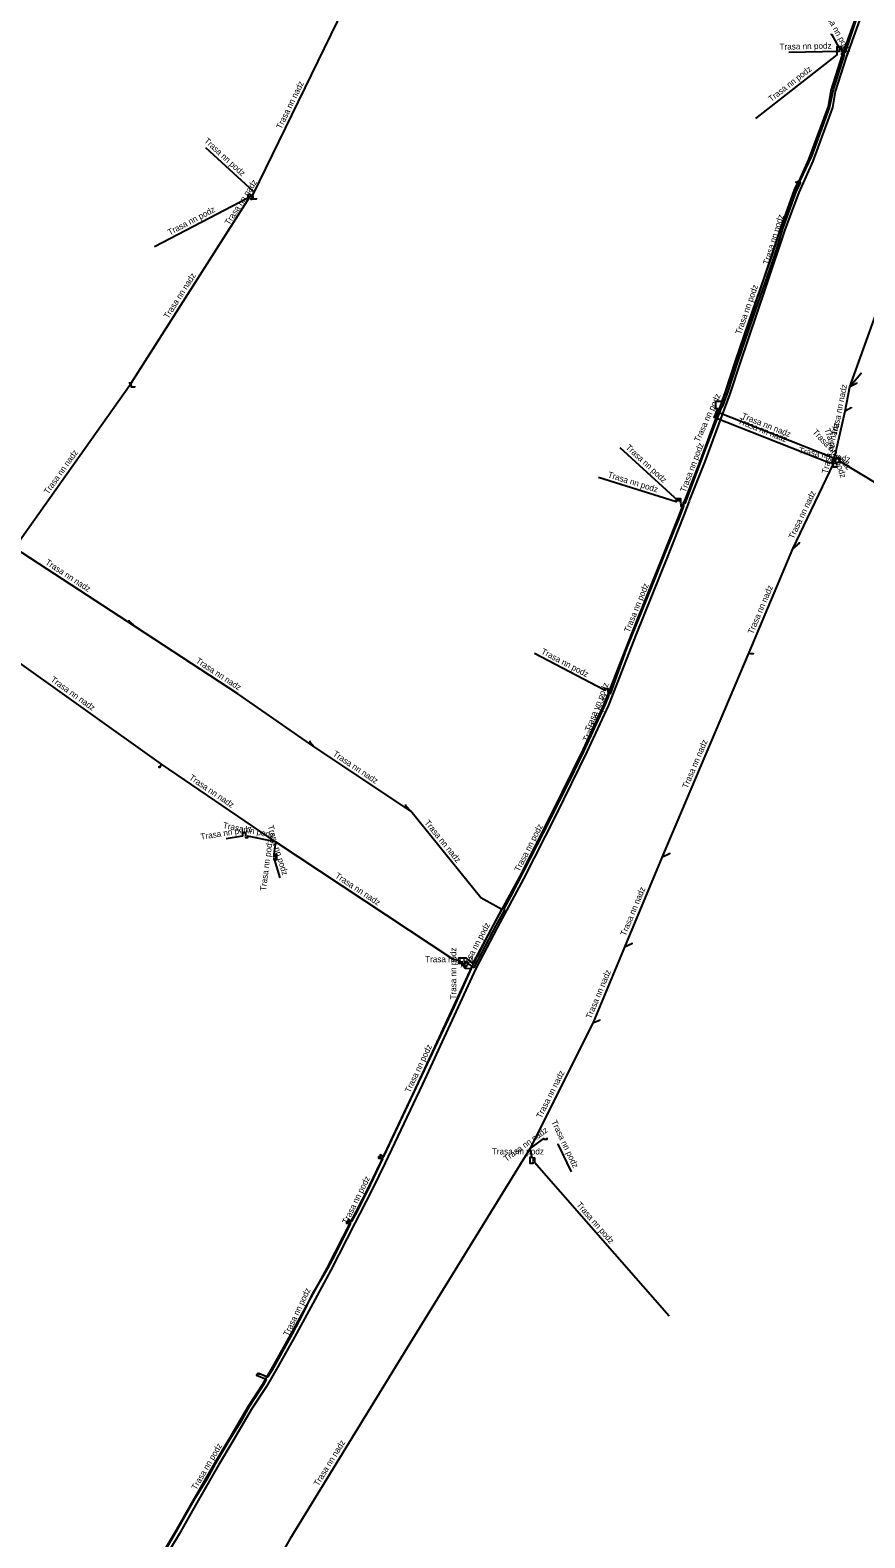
# Model space of a CAD drawing. Extents: x -742082 to -717476, y -1040737 to -1024597.
# Drawn here: x -736274.4 to -736137.3, y -1032679.3 to -1032431.7 of the extents above; entities that cross this region are included whole.
import ezdxf

# ---------------------------------------------------------------- set-up
doc = ezdxf.new("R2010")
doc.units = 0
for name, color, linetype in [('Level 13', 7, 'Continuous'), ('Level 14', 7, 'Continuous'), ('Level 15', 7, 'Continuous'), ('Level 20', 7, 'Continuous'), ('Level 25', 7, 'Continuous')]:
    doc.layers.add(name, color=color, linetype=linetype)

msp = doc.modelspace()

# ---------------------------------------------------------------- linework, layer by layer
at = {"layer": 'Level 13'}
for p, q in [((-736237.89, -1032458.82), (-736237.87, -1032458.79)), ((-736276.98, -1032516.71), (-736257.81, -1032489.67)), ((-736140.6, -1032494.3), (-736139.8, -1032490.3)), ((-736142.56, -1032502.91), (-736140.6, -1032494.3)), ((-736104.86, -1032524.63), (-736141.51, -1032502.48)), ((-736257.1, -1032529.7), (-736276.98, -1032516.71)), ((-736211.9, -1032560), (-736227.8, -1032549.4)), ((-736234.1, -1032565), (-736252.87, -1032552.27)), ((-736200.42, -1032574.18), (-736211.9, -1032560)), ((-736204.86, -1032584.4), (-736234.1, -1032565))]:
    msp.add_line(p, q, dxfattribs=at)
for points in [[(-736237.87, -1032458.79), (-736222.83, -1032428.06), (-736222.14, -1032428.06), (-736222.14, -1032427.26), (-736222.34, -1032427.08)], [(-736139.8, -1032490.3), (-736135.3, -1032477.8), (-736127.6, -1032456.1)], [(-736257.81, -1032489.67), (-736238.35, -1032459.07), (-736237.89, -1032458.82)], [(-736238.2, -1032459.3), (-736238.2, -1032459.45), (-736237.94, -1032459.46), (-736237.87, -1032458.79)], [(-736237.8, -1032458.4), (-736237.8, -1032458.51), (-736237.87, -1032458.79)], [(-736237.3, -1032459.3), (-736237.3, -1032459.46), (-736237.75, -1032459.46), (-736237.87, -1032458.79)], [(-736138, -1032488), (-736138, -1032488.15), (-736139.8, -1032490.3)], [(-736258.1, -1032489.5), (-736258.1, -1032489.66), (-736257.81, -1032489.67)], [(-736257.3, -1032490.2), (-736257.3, -1032490.36), (-736257.75, -1032490.36), (-736257.81, -1032489.67)], [(-736138.7, -1032489.6), (-736138.7, -1032489.74), (-736139.8, -1032490.3)], [(-736139.6, -1032493.6), (-736139.6, -1032493.76), (-736140.6, -1032494.3)], [(-736141.76, -1032502.55), (-736141.5, -1032502.71), (-736141.5, -1032502), (-736142.06, -1032502), (-736142.35, -1032502.59)], [(-736148.1, -1032515.8), (-736148.1, -1032515.96), (-736149.2, -1032516.9)], [(-736258.2, -1032528.6), (-736258.2, -1032528.76), (-736257.1, -1032529.7)], [(-736227.8, -1032549.4), (-736240.3, -1032540.7), (-736257.1, -1032529.7)], [(-736252.87, -1032552.27), (-736278.83, -1032533.68), (-736278.83, -1032533.2), (-736279.5, -1032533.2)], [(-736155.7, -1032534), (-736155.7, -1032534.16), (-736156.15, -1032534.16), (-736156.4, -1032533.9)], [(-736228.5, -1032548.4), (-736228.5, -1032548.56), (-736227.8, -1032549.4)], [(-736253.3, -1032552.6), (-736253.3, -1032552.76), (-736253.05, -1032552.76), (-736252.87, -1032552.27)], [(-736212.8, -1032558.9), (-736212.8, -1032559.06), (-736211.9, -1032560)], [(-736169.4, -1032566.8), (-736169.4, -1032566.96), (-736170.7, -1032567.6)], [(-736175.6, -1032581.6), (-736175.6, -1032581.76), (-736176.8, -1032582.3)], [(-736180.9, -1032594.2), (-736180.9, -1032594.36), (-736182, -1032594.8)]]:
    msp.add_lwpolyline(points, dxfattribs=at)
at = {"layer": 'Level 14'}
for p, q in [((-736142.56, -1032502.91), (-736149.2, -1032516.9)), ((-736149.2, -1032516.9), (-736156.4, -1032533.9)), ((-736156.4, -1032533.9), (-736170.7, -1032567.6)), ((-736170.7, -1032567.6), (-736176.8, -1032582.3)), ((-736176.8, -1032582.3), (-736182, -1032594.8)), ((-736182, -1032594.8), (-736192.37, -1032615.41))]:
    msp.add_line(p, q, dxfattribs=at)
for points in [[(-736142.7, -1032502.73), (-736143.11, -1032502.83), (-736162.06, -1032495.31), (-736161.88, -1032494.84)], [(-736142.7, -1032502.73), (-736142.58, -1032501.96), (-736161.7, -1032494.38), (-736161.88, -1032494.84)], [(-736192.37, -1032615.41), (-736190.05, -1032613.73), (-736190.05, -1032613.85), (-736189.5, -1032613.85), (-736189.5, -1032613.6)], [(-736192.37, -1032615.41), (-736212.52, -1032648.12), (-736231.78, -1032679.53), (-736253.18, -1032716.9)]]:
    msp.add_lwpolyline(points, dxfattribs=at)
at = {"layer": 'Level 15'}
for points in [[(-736141.1, -1032435.4), (-736140.74, -1032435.66), (-736140.74, -1032435.21), (-736140.54, -1032435.31), (-736138.3, -1032428.6), (-736133.52, -1032414.82), (-736130.87, -1032408.68), (-736127.11, -1032401.5), (-736127.29, -1032400.74), (-736128.02, -1032399.11), (-736127.76, -1032399.12), (-736127.76, -1032398.75)], [(-736141.13, -1032435.29), (-736141.13, -1032434.45), (-736141.95, -1032434.45), (-736141.95, -1032435.79), (-736155.3, -1032446.2)], [(-736141.1, -1032435.29), (-736141.1, -1032434.55), (-736141.56, -1032434.55), (-736142.7, -1032432.46), (-736142.8, -1032432.46), (-736142.8, -1032432.3)], [(-736160.99, -1032493.36), (-736160.99, -1032493.62), (-736160.8, -1032493.62), (-736160.6, -1032493.32), (-736159.77, -1032491.08), (-736158.21, -1032486.19), (-736155.31, -1032477.73), (-736152.11, -1032468.66), (-736150.73, -1032464.18), (-736148.54, -1032458.09), (-736147.93, -1032456.84), (-736147.97, -1032456.44), (-736146.06, -1032452.43), (-736143.15, -1032444.45), (-736142.5, -1032441.48), (-736140.69, -1032435.76), (-736141.1, -1032435.76), (-736141.1, -1032435.4)], [(-736141.08, -1032435.29), (-736141.08, -1032434.85), (-736141.55, -1032434.85), (-736141.55, -1032435.21), (-736149.8, -1032435.4)], [(-736245.6, -1032451), (-736237.8, -1032458.14), (-736237.8, -1032458.29)], [(-736161.07, -1032493.36), (-736161.07, -1032493.92), (-736161.82, -1032493.92), (-736161.82, -1032492.62), (-736160.76, -1032492.62), (-736160.15, -1032490.95), (-736158.59, -1032486.07), (-736155.69, -1032477.6), (-736152.49, -1032468.53), (-736151.11, -1032464.05), (-736148.91, -1032457.94), (-736148.28, -1032456.65), (-736148.38, -1032456.58), (-736148.38, -1032456.71), (-736148.64, -1032456.71), (-736148.64, -1032456.56)], [(-736238.2, -1032459.19), (-736238.2, -1032458.74), (-736238.65, -1032458.75), (-736238.65, -1032459.28), (-736254, -1032467.3)], [(-736161.02, -1032493.36), (-736161.02, -1032493.72), (-736160.96, -1032493.72), (-736163.67, -1032500.87), (-736166.91, -1032509.42), (-736167.2, -1032509.31), (-736167.1, -1032509.81), (-736167.55, -1032509.55)], [(-736161.88, -1032494.84), (-736161.42, -1032493.82), (-736161.04, -1032493.82), (-736161.04, -1032493.36)], [(-736167.54, -1032509.45), (-736167.54, -1032509), (-736168, -1032509), (-736168, -1032509.03), (-736177.5, -1032500.3)], [(-736142, -1032503.3), (-736142, -1032503.46), (-736142.45, -1032503.46), (-736142.7, -1032502.73)], [(-736142.56, -1032502.91), (-736142.45, -1032502.75), (-736142.01, -1032502.83), (-736142.01, -1032503.19)], [(-736141.76, -1032502.55), (-736141.76, -1032502.71), (-736142.09, -1032502.71), (-736141.99, -1032502.82), (-736141.99, -1032503.19)], [(-736167.56, -1032509.45), (-736167.56, -1032508.7), (-736168.3, -1032508.7), (-736168.3, -1032509.15), (-736181.1, -1032505.2)], [(-736167.55, -1032509.55), (-736167.55, -1032509.91), (-736167.1, -1032509.91), (-736167.8, -1032511.62), (-736170.17, -1032517.62), (-736172.31, -1032522.95), (-736176.54, -1032533.37), (-736179.17, -1032540.72), (-736179.52, -1032540.56)], [(-736179.52, -1032540.45), (-736179.52, -1032539.91), (-736180.07, -1032539.91), (-736180.07, -1032540.12), (-736191.6, -1032534.1)], [(-736179.52, -1032540.56), (-736179.52, -1032540.92), (-736179.38, -1032540.92), (-736180.01, -1032542.4), (-736183.55, -1032550.18), (-736185.06, -1032553.34), (-736189.1, -1032561.41), (-736195.53, -1032573.97), (-736196.59, -1032575.91), (-736196.58, -1032576.31), (-736197.92, -1032578.75), (-736201.58, -1032585.64), (-736203.03, -1032584.59), (-736203.03, -1032585.08), (-736203.45, -1032585.08), (-736203.45, -1032584.61)], [(-736239, -1032564.09), (-736239, -1032563.55), (-736239.55, -1032563.55), (-736239.55, -1032564.07), (-736242.2, -1032564.5)], [(-736234.1, -1032565), (-736238.74, -1032564.07), (-736238.74, -1032564.36), (-736239, -1032564.36), (-736239, -1032564.2)], [(-736234.1, -1032565), (-736234.38, -1032567.03), (-736233.98, -1032567.03), (-736233.98, -1032567.94), (-736234.34, -1032567.94), (-736234.34, -1032567.68)], [(-736234.34, -1032567.57), (-736234.34, -1032567.13), (-736234.08, -1032567.13), (-736234.08, -1032567.84), (-736234.33, -1032567.84), (-736233.4, -1032570.9)], [(-736203.42, -1032584.61), (-736203.42, -1032584.98), (-736204.04, -1032584.98), (-736204.04, -1032584.07), (-736202.83, -1032584.07), (-736201.72, -1032585.03), (-736198.27, -1032578.56), (-736196.93, -1032576.11), (-736200.42, -1032574.18)], [(-736203.47, -1032584.61), (-736203.47, -1032585.18), (-736203.2, -1032585.18), (-736203.21, -1032585.48), (-736202.98, -1032585.74), (-736201.99, -1032585.83), (-736204.82, -1032592.17), (-736216.39, -1032616.71), (-736216.96, -1032616.43), (-736216.86, -1032616.84), (-736217.21, -1032616.68)], [(-736203.4, -1032584.61), (-736203.4, -1032584.88), (-736203.94, -1032584.88), (-736203.94, -1032584.49), (-736204.86, -1032584.4)], [(-736203.5, -1032584.61), (-736203.5, -1032585.28), (-736203.14, -1032585.28), (-736203.14, -1032585.42), (-736202.69, -1032585.42), (-736202.69, -1032585.26)], [(-736185.5, -1032619.2), (-736187.63, -1032614.76), (-736187.7, -1032614.76), (-736187.7, -1032614.6)], [(-736217.21, -1032616.68), (-736217.21, -1032616.94), (-736216.86, -1032616.94), (-736216.86, -1032616.93), (-736216.56, -1032617.07), (-736218.56, -1032621.36), (-736220.69, -1032625.69), (-736221.65, -1032627.34), (-736222.18, -1032627.09), (-736222.08, -1032627.51), (-736222.44, -1032627.35)], [(-736192.37, -1032615.41), (-736192.01, -1032616.85), (-736192.35, -1032616.85), (-736192.35, -1032617.76), (-736191.8, -1032617.76), (-736191.8, -1032617.5)], [(-736169.5, -1032642.9), (-736191.59, -1032617.66), (-736191.55, -1032617.66), (-736191.55, -1032616.95), (-736191.8, -1032616.95), (-736191.8, -1032617.39)], [(-736222.44, -1032627.35), (-736222.44, -1032627.61), (-736222.08, -1032627.61), (-736222.08, -1032627.58), (-736221.83, -1032627.69), (-736224.4, -1032632.83), (-736225.58, -1032635.08), (-736228.28, -1032639.63), (-736229.64, -1032642.49), (-736231.4, -1032645.81), (-736234.75, -1032651.85), (-736235.45, -1032652.92), (-736236.84, -1032652.34), (-736236.74, -1032652.45), (-736237.09, -1032652.29)], [(-736237.09, -1032652.29), (-736237.09, -1032652.55), (-736237.27, -1032652.55), (-736237.26, -1032652.6), (-736235.65, -1032653.27), (-736236, -1032653.98), (-736238.44, -1032657.74), (-736239.89, -1032660.3), (-736241.65, -1032663.1), (-736244.01, -1032667.14), (-736245.39, -1032669.68), (-736247.52, -1032673.15), (-736250.48, -1032678.34), (-736251.97, -1032680.91), (-736252.08, -1032681.19), (-736252.43, -1032681.03)]]:
    msp.add_lwpolyline(points, dxfattribs=at)
at = {"layer": 'Level 25'}
for points in [[(-736254.49, -1032684.89), (-736250.57, -1032678.34), (-736247.64, -1032673.23), (-736244.07, -1032667.05), (-736241.74, -1032663.08), (-736238.54, -1032657.67), (-736236.22, -1032654.09), (-736234.36, -1032650.85), (-736231.64, -1032646.02), (-736228.28, -1032639.86), (-736225.64, -1032635), (-736221.7, -1032627.29), (-736220.89, -1032625.75), (-736218.8, -1032621.7), (-736216.72, -1032617.41), (-736210.64, -1032604.52), (-736201.83, -1032585.51), (-736198.3, -1032578.67), (-736194.01, -1032570.74), (-736188.74, -1032560.33), (-736183.61, -1032549.92), (-736180.08, -1032542.28), (-736175.57, -1032530.68), (-736170.27, -1032517.6), (-736167.75, -1032511.14), (-736166.86, -1032508.8), (-736166.76, -1032508.59), (-736164.28, -1032502.3), (-736160.2, -1032491.21), (-736158.52, -1032486.2), (-736154.31, -1032473.76), (-736151.09, -1032464.08), (-736148.84, -1032458.11), (-736146.56, -1032452.95), (-736143.33, -1032444.26), (-736142.87, -1032441.64), (-736141.07, -1032435.91), (-736138.16, -1032427.86)], [(-736137.5, -1032428.1), (-736140.41, -1032436.13), (-736142.19, -1032441.81), (-736142.65, -1032444.44), (-736145.91, -1032453.21), (-736148.19, -1032458.37), (-736150.43, -1032464.32), (-736153.65, -1032473.98), (-736157.85, -1032486.43), (-736159.54, -1032491.44), (-736163.63, -1032502.55), (-736166.12, -1032508.86), (-736166.21, -1032509.07), (-736167.09, -1032511.39), (-736169.62, -1032517.86), (-736174.92, -1032530.93), (-736179.44, -1032542.55), (-736182.98, -1032550.23), (-736188.11, -1032560.64), (-736193.39, -1032571.06), (-736197.68, -1032579), (-736201.21, -1032585.82), (-736210, -1032604.82), (-736216.09, -1032617.71), (-736218.17, -1032622.01), (-736220.27, -1032626.07), (-736221.08, -1032627.62), (-736225.02, -1032635.33), (-736227.66, -1032640.2), (-736231.03, -1032646.36), (-736233.76, -1032651.2), (-736235.63, -1032654.45), (-736237.94, -1032658.03), (-736241.14, -1032663.43), (-736243.46, -1032667.4), (-736247.03, -1032673.58), (-736249.96, -1032678.69), (-736253.89, -1032685.24)]]:
    msp.add_lwpolyline(points, dxfattribs=at)

# ---------------------------------------------------------------- texts
at = {"layer": 'Level 20'}
for s, rotation, p in [('Trasa nn podz', 298.6738, (-736144.48, -1032428.16)), ('Trasa nn podz', 1.3128, (-736151.34, -1032434.94)), ('Trasa nn podz', 37.9576, (-736152.71, -1032443.54)), ('Trasa nn nadz', 63.9281, (-736233.18, -1032448.06)), ('Trasa nn podz', 317.5255, (-736245.94, -1032450.01)), ('Trasa nn nadz', 57.1589, (-736241.71, -1032463.82)), ('Trasa nn podz', 27.5777, (-736251.5, -1032465.43)), ('Trasa nn podz', 72.884, (-736153.15, -1032470.32)), ('Trasa nn nadz', 57.5433, (-736251.74, -1032479.19)), ('Trasa nn podz', 70.5611, (-736157.69, -1032481.77)), ('Trasa nn podz', 65.5271, (-736164.53, -1032499.46)), ('Trasa nn nadz', 78.6901, (-736141.92, -1032498.37)), ('Trasa nn nadz', 338.3556, (-736158.28, -1032496.27)), ('Trasa nn nadz', 338.3555, (-736157.66, -1032495.44)), ('Trasa nn nadz', 77.1787, (-736143.46, -1032504.62)), ('Trasa nn podz', 313.2674, (-736146.02, -1032497.8)), ('Trasa nn podz', 288.7376, (-736144.02, -1032497.27)), ('Trasa nn nadz', 54.6653, (-736271.44, -1032508.03)), ('Trasa nn podz', 317.4053, (-736176.7, -1032500.36)), ('Trasa nn podz', 69.2408, (-736166.79, -1032507.7)), ('Trasa nn podz', 349.7153, (-736148.24, -1032501.19)), ('Trasa nn podz', 342.8343, (-736179.64, -1032505.13)), ('Trasa nn nadz', 64.6123, (-736149.03, -1032515.37)), ('Trasa nn nadz', 326.8386, (-736272.03, -1032519.35)), ('Trasa nn podz', 67.9149, (-736176, -1032530.71)), ('Trasa nn nadz', 67.0459, (-736155.71, -1032530.99)), ('Trasa nn podz', 332.4147, (-736190.6, -1032534.06)), ('Trasa nn nadz', 326.7847, (-736247.31, -1032535.51)), ('Trasa nn nadz', 324.3917, (-736271.14, -1032538.57)), ('Trasa vn podz', 65.2329, (-736182.82, -1032548.69)), ('Trasa vn podz', 68.7276, (-736182.45, -1032546.98)), ('Trasa nn nadz', 67.0069, (-736166.47, -1032556.34)), ('Trasa nn nadz', 326.3099, (-736224.8, -1032550.8)), ('Trasa nn nadz', 325.8545, (-736248.41, -1032554.69)), ('Trasa nn podz', 9.1627, (-736246.36, -1032564.67)), ('Trasa nn podz', 348.6901, (-736242.83, -1032562.74)), ('Trasa nn podz', 286.8621, (-736235.45, -1032562.42)), ('Trasa nn nadz', 308.9933, (-736209.73, -1032561.89)), ('Trasa nn podz', 62.8939, (-736194.07, -1032570.01)), ('Trasa nn podz', 82.291, (-736235.71, -1032573.13)), ('Trasa nn nadz', 326.4367, (-736224.44, -1032570.81)), ('Trasa nn nadz', 67.4632, (-736176.62, -1032580.56)), ('Trasa nn podz', 61.96, (-736202.87, -1032586.14)), ('Trasa nn podz', 90, (-736204.44, -1032590.91)), ('Trasa nn nadz', 67.4127, (-736182.28, -1032594.16)), ('Trasa nn podz', 64.7463, (-736212.03, -1032606.3)), ('Trasa nn nadz', 63.2906, (-736190.46, -1032610.5)), ('Trasa nn nadz', 35.9654, (-736196.22, -1032617.58)), ('Trasa nn podz', 295.6022, (-736188.88, -1032610.99)), ('Trasa nn podz', 360, (-736198.59, -1032616.35)), ('Trasa nn podz', 63.7752, (-736222.33, -1032627.88)), ('Trasa nn podz', 311.1859, (-736184.78, -1032624.68)), ('Trasa nn podz', 64.5195, (-736232, -1032646.29)), ('Trasa nn podz', 59.7806, (-736247.14, -1032671.53)), ('Trasa nn nadz', 58.4842, (-736227.08, -1032670.9))]:
    msp.add_text(s, height=1, rotation=rotation, dxfattribs=at).set_placement(p)
msp.add_text('Trasa nn podz', height=1, dxfattribs=at).set_placement((-736209.56, -1032584.78))

doc.saveas('drawing.dxf')
